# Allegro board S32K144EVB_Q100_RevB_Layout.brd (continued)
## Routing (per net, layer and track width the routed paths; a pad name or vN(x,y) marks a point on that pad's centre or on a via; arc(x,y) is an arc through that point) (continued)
P3V3: length 35
  TOP w0.381: 49.22,30.18 U15.5 ; U15.5 49.22,29.71 ; U15.5 50.59,29.71 ; U15.5 49.22,30.66 ; U15.5 50.59,30.66 ; U15.5 49.9,29.65 ; U15.5 50.59,30.18 ; U15.5 49.9,30.71 ; TP13.1 44.15,26.79 ; TP13.1 43.68,26.89 ; TP13.1 44.15,25.85 ; TP13.1 44.25,26.32 ; TP13.1 43.68,25.75 ; TP13.1 43.11,26.32 ; TP13.1 43.21,26.79 ; TP13.1 43.21,25.85 ; 42.73,33.75 J10.1 ; J10.1 44.64,32.79 ; J10.1 42.73,32.79 ; J10.1 43.69,32.79 ; J10.1 43.69,34.7 ; J10.1 44.64,33.75 ; J10.1 42.73,34.7 ; J10.1 44.64,34.7 ; 47.08,33.65 R63.1 ; R63.1 47.85,34.29 ; R63.1 46.32,33.65 ; R63.1 46.32,34.29 ; R63.1 47.85,33.65 ; R63.1 46.7,33.65 ; 50.95,29.8 C24.1 ; C24.1 51.72,29.8 ; C24.1 52.1,29.8 ; C24.1 52.48,29.16 ; C24.1 52.48,29.8 ; C24.1 50.95,29.16
  L3_MIX w0.508: J3.7 35.52,6.15 ; J3.7 34.49,5.12 ; J3.7 36.31,5.91 ; J3.7 36.55,5.12 ; J3.7 34.73,5.91
  vias: v1(40.9,27.01) v1(40.89,26.22) v1(40.91,25.42)
P3V3_SDA: length 34.8
  TOP w0.254: 31.01,35.52 C19.1 30.5,36.03 ; C18.1 29.93,36.03 ; C18.1 29.42,36.54 ; C18.1 29.42,35.52 ; v1(30.04,45.2) 30.3,45.46 R15.1 ; U1.1 9.07,51.26 ; U2.7 28.45,46.1 v1(28.2,45.85) 28.54,45.51 U4.1 ; 30.51,37.11 R52.1 ; 9.19,49.94 C3.1 ; U9.5 v1(33.7,39.65) ; v1(27.83,41.93) 27.86,41.93 28.13,41.66 U7.1 ; U8.11 v1(16.65,37.9) ; U8.1 v1(19.51,43.09) ; 15.64,40.52 16.01,40.88 16.58,40.88 16.94,40.52 ; R1.2 v1(6.4,52.28) ; U10.1 v1(27.41,38.62) ; 9.19,50.89 R3.1
  TOP w0.508: R60.1 v1(11.75,37.33) ; v1(37.61,42.64) C10.1 37.61,41.46 R39.2 R42.1 ; R77.1 v1(15.03,27.14) ; 15.64,40.52 C12.1 13.35,40.52 J9.1 ; C26.1 J12.1 ; R12.1 v1(25.56,46.72) ; R30.1 v1(30.99,42.98)
  TOP w0.635: v1(19.51,43.09) 18.65,43.95 C7.1 17.76,44.83 C6.1
  BOTTOM w0.254: 17.32,27.42 J12.1 17.99,28.09 ; J9.1 12.69,38.9 ; J9.1 10.78,38.9 ; J9.1 11.73,37.94
  vias: v1(8.76,50.56) v1(29.29,36.97)
P5V0: length 36.2
  TOP w0.254: 43.47,29.71 R169.1 ; R169.1 43.89,29.8 ; R169.1 44.31,29.71 ; R169.1 43.38,29.29
  TOP w0.381: 37.99,30.48 TP14.1 ; TP14.1 38.92,30.48 ; TP14.1 38.92,29.54 ; TP14.1 39.03,30.01 ; TP14.1 38.46,30.58 ; C22.1 42.88,29.83 ; C22.1 41.36,29.83 ; C22.1 42.12,30.47 ; C22.1 42.88,30.47 ; C22.1 41.36,30.47 ; 38.61,35.53 R64.1 ; R64.1 37.98,36.29 ; R64.1 37.98,35.53 ; U15.1 47.31,30.71 ; U15.1 48,30.18 ; U15.1 46.63,30.66 ; U15.1 46.63,30.18 ; U15.1 48,30.66 ; J10.3 38.61,34.7 ; J10.3 37.65,33.75 ; J10.3 37.87,34.48 ; J10.3 38.61,32.79 ; J10.3 39.34,33.01 ; J10.3 37.87,33.01 ; C21.1 41.07,29.83 ; C21.1 41.07,30.47 ; C21.1 39.54,29.83 ; C21.1 40.3,30.47 ; C21.1 39.54,30.47
  TOP w0.508: D4.A v2(30.01,29.88)
  L3_MIX w0.508: J3.9 38.85,5.91 ; J3.9 38.06,6.15 ; J3.9 39.09,5.12
  BOTTOM w0.254: 37.65,33.75 J10.3 ; J10.3 39.56,33.75 ; J10.3 38.61,32.79 ; 30.71,33.75 J107.2 ; J107.2 31.66,32.8 ; J107.2 32.61,33.75
  vias: v1(42.3,30.8) v1(43.1,31.39) v1(43.08,30.51) v2(38.62,31.09)
P5V0_SDA_USB_CONN_VBUS: length 5.6
  TOP w0.356: 5.64,42.72 J7.1
  TOP w0.635: 5.64,42.72 6.92,41.44 U6.1 L1.1
P5V_SDA: length 24.5
  TOP w0.254: v1(16.62,41.43) 16.74,41.43 U8.6 ; 22.67,45.86 R14.1 22.16,45.36
  TOP w0.508: C11.1 v1(9.35,38.48) ; L1.2 v1(7.18,38.88) 7.18,37.79 7.5,37.47 C15.1 ; U11.1 v1(8.08,31.93) ; R70.1 v1(8.14,31.06) ; C25.1 v1(8.15,29.82) ; R57.1 v1(26.57,37.38)
  L3_MIX w0.635: v1(16.62,41.43) v1(16.62,45.82)
  BOTTOM w0.254: v1(22.02,45.89) 22.47,45.44 22.47,39.84 23.1,39.21 24.74,39.21 25.5,38.45 25.53,38.45 25.9,38.08 25.9,38.05 v1(26.57,37.38)
  vias: v1(7.36,46.09) v1(8.23,46.11) v1(9.16,46.11)
P5V_SDA_PSW: length 34.4
  TOP w0.508: v1(7.96,27.05) 7.26,27.75 7.26,34.41 8.08,35.23 U11.6
  BOTTOM w0.508: v1(7.96,27.05) 9.59,27.05 11.2,25.44 20.81,25.44 J107.3
VBATT: length 88
  TOP w0.381: 22.29,7.96 J16.1 ; J16.1 23.2,11.8 ; J16.1 23.2,10.84 ; J16.1 22.75,11.8 ; J16.1 23.2,7.96 ; J16.1 23.2,9.88 ; J16.1 22.29,11.8 ; J16.1 21.83,7.96 ; 26.4,10.48 D9.A ; D9.A 26.4,12.08 ; D9.A 25.55,10.5 ; D9.A 25.55,11.28 ; D9.A 25.98,10.49 ; D9.A 25.55,12.07 ; TP38.1 26.26,9.05 ; TP38.1 25.69,9.62 ; TP38.1 26.15,8.58 ; TP38.1 25.22,8.58 ; TP38.1 25.69,8.48 ; TP38.1 25.22,9.52 ; TP38.1 25.12,9.05 ; TP38.1 26.15,9.52
  TOP w0.508: R110.1 v1(45.2,14.57)
  BOTTOM w0.635: v1(45.2,14.57) 37.33,14.57 34.96,12.2 28.83,12.2 v2(26.61,9.98)
  BOTTOM w1.016: J11.2 4.8,31.29 4.8,14.56 12.16,7.2 v3(23.93,7.2)
VDD: length 106
  TOP w0.254: 103.64,13.82 D11.A3 ; D11.A3 104.83,14.81 ; D11.A3 104.83,12.83 ; 104.83,10.73 D11.A2 ; D11.A2 103.64,11.72 ; D11.A2 104.83,12.71 ; 104.83,8.63 D11.A1 ; D11.A1 103.64,9.62 ; D11.A1 104.83,10.61
  TOP w0.508: J10.2 42.1,33.75 ; J10.2 41.88,34.48 ; J10.2 40.19,33.75 ; J10.2 40.41,34.48 ; J10.2 41.15,34.7 ; R64.2 40.77,36.29 ; R64.2 40.13,37.05 ; R64.2 40.13,35.53 ; J15.1 52.57,36.39 ; J15.1 51.62,36.39 ; J15.1 50.67,36.39 ; J15.1 52.57,35.44 ; J15.1 50.67,35.44 ; R121.1 48.93,37.77 ; R121.1 48.17,37.13 ; R121.1 47.4,37.77 ; 42.73,37.13 TP9.1 ; TP9.1 42.95,37.87 ; TP9.1 44.42,36.4 ; TP9.1 43.69,36.18 ; TP9.1 44.42,37.87 ; TP9.1 43.69,38.09 ; TP9.1 44.64,37.13 ; TP9.1 42.95,36.4 ; 48.28,35.81 R117.1 ; R117.1 49.8,35.81 ; R117.1 49.04,36.45 ; R63.2 47.85,35.81 ; R63.2 46.32,35.81 ; R63.2 47.08,36.45 ; 53.16,38.62 J14.1 ; J14.1 53.83,39.29 ; J14.1 53.83,38.62 ; J25.4 v2(99.68,33.62) ; 40.46,37.55 SH1.2 41.15,38.15 ; SW2.4 v1(105.08,30.97) ; SW3.2 v1(105.08,27.21) ; R56.2 v1(34.58,10.46) ; SW2.2 v1(105.08,38.79) ; SW3.4 v1(105.08,19.63)
  TOP w0.635: v2(94.05,35.92) J25.1 ; J3.3 C49.1
  L3_MIX w0.508: J3.3 31.23,5.91 ; J3.3 29.65,4.33 ; J3.3 29.41,5.12 ; J3.3 31.47,5.12 ; J3.3 29.65,5.91 ; J3.3 31.23,4.33 ; J3.3 30.44,4.09 ; J3.3 30.44,6.15 ; J10.2 41.88,33.01 ; J10.2 42.1,33.75 ; J10.2 40.19,33.75 ; J10.2 40.41,33.01 ; J10.2 40.41,34.48 ; J10.2 41.88,34.48 ; J10.2 41.15,32.79 ; J10.2 41.15,34.7 ; 42.73,37.13 TP9.1 ; TP9.1 42.95,37.87 ; TP9.1 43.69,38.09 ; TP9.1 43.69,36.18 ; TP9.1 42.95,36.4
  BOTTOM w0.508: J6.10 82.27,55.92 ; J6.10 81.24,54.89 ; J6.10 80.21,55.92 ; J6.10 81.24,56.95 ; 104.47,28.25 TP16.1 ; TP16.1 105.42,29.2 ; TP16.1 103.51,29.2 ; TP16.1 104.47,30.16 ; TP4.1 101.71,51.62 ; TP4.1 100.76,50.66 ; TP4.1 100.76,52.57 ; TP4.1 99.81,51.62 ; 82.75,2.58 J5.10 ; J5.10 83.78,3.61 ; J5.10 84.81,2.58 ; J5.10 83.78,1.55 ; 100.74,47.6 R13.1 ; R13.1 101.76,48.62 ; R13.1 101.76,46.59 ; R13.1 102.78,47.6
  BOTTOM w0.635: 102.88,34.66 100.73,34.66 v2(99.68,33.62) 96.35,33.62 v2(94.05,35.92)
  vias: v1(70.12,3.11) v1(70.13,2.07) v1(70.11,1.03) v1(71.49,2.07) v1(71.57,3.08) v1(71.58,1.03) v1(103.39,14.2) v1(103.39,11.98) v1(104.21,15.06) v1(104.23,8.3)
VDD_MCU: length 70.8
  TOP w0.254: C43.1 59.51,39.33 ; C43.1 58.87,39.33 ; C43.1 59.51,38.57 ; C43.1 58.87,37.81 ; C43.1 59.51,37.81 ; R103.1 58.95,33.62 ; R103.1 58.18,33.62 ; R103.1 58.95,32.98 ; R103.1 57.42,33.62 ; R103.1 57.42,32.98 ; 60.97,33.2 C144.1 ; C144.1 61.91,32.78 ; C144.1 61.06,32.78 ; C144.1 61.48,32.69 ; C144.1 61.99,33.2 ; C144.1 61.06,33.63 ; 63.24,32.78 C145.1 ; C145.1 64.09,32.78 ; C145.1 64.18,33.2 ; C145.1 63.16,33.2 ; C145.1 63.67,32.69 ; C147.1 59.51,40.3 ; C147.1 59.51,41.83 ; C147.1 58.23,40.3 ; C147.1 58.87,41.83 ; C147.1 58.23,41.06 ; C147.1 58.23,41.83 ; C147.1 59.51,41.06 ; C147.1 58.87,40.3 ; R99.1 60.56,33.63 ; R99.1 60.56,32.99 ; R99.1 59.04,33.63 ; R99.1 59.04,32.99 ; R99.1 59.8,33.63 ; 75.87,38.75 U17.87 ; C129.1 59.51,35.22 ; C129.1 59.51,34.46 ; C129.1 59.51,35.98 ; C129.1 58.87,34.46 ; C129.1 58.87,35.98 ; 84.68,28.16 U17.61 81.54,28.16 ; C140.1 63.08,33.2 ; C140.1 62.15,32.78 ; C140.1 62.58,32.69 ; C140.1 63,32.78 ; C140.1 62.07,33.2 ; C131.1 59.51,36.13 ; C131.1 58.87,37.66 ; C131.1 59.51,36.89 ; C131.1 59.51,37.66 ; C131.1 58.87,36.13 ; 75.37,19.77 U17.38
  TOP w0.381: 84.68,28.16 84.91,28.39 C143.1 ; C141.1 75.62,19.51 75.37,19.77 ; C142.1 75.62,39 75.87,38.75
  TOP w0.508: C146.1 86.48,28.55 86.31,28.39 C143.1
  TOP w0.635: C141.1 75.62,18.53 v2(75.2,18.11) 75.24,18.07 C137.1 ; v2(75.12,28.16) 81.54,28.16 ; C142.1 v2(75.62,40.4) 75.62,41.02 C133.1
  TOP w0.762: R117.2 49.17,34.29 50.56,32.9 J15.2
  BOTTOM w0.508: v1(68.89,30.41) v2(65.79,30.41)
  BOTTOM w1.016: J15.2 53.23,32.9 54.28,33.95 v3(57.38,33.95)
  vias: v2(75.12,30.66)
VIN: length 26.4
  TOP w0.762: D13.A J3.15 44.18,6.62 36.82,6.62 34.16,9.29 29.68,9.29 27.9,7.51 J3.1
ADC0_SE12: length 59.1
  TOP w0.16: R13.2 C5.1 97.69,44.54 97.69,44.54 TP5.1 v1(97.69,42.01) ; R164.2 v1(80.45,13.79)
  L3_MIX w0.16: v1(97.69,42.01) 102.17,37.53 102.17,31.06 102.77,30.46 102.77,18.33 99.99,15.55 v1(96.99,15.55)
  BOTTOM w0.16: v1(96.99,15.55) 95.1,13.65 89.65,13.65 89,14.3 85.66,14.3 84.82,13.47 80.78,13.47 v1(80.45,13.79)
AREF: length 44.2
  TOP w0.508: R109.2 55.67,44.7 53.32,47.06 35.01,47.06 32.76,49.31 26.69,49.31 23.84,52.16 J2.15
BTN0: length 50.2
  TOP w0.16: R152.2 v1(84.64,14.09) ; SW2.3 SW2.1 C16.1 R44.1 v1(100.03,38.61)
  L3_MIX w0.16: v1(99.26,17.01) 102.15,19.91 102.15,29.99 101.53,30.62 101.53,37.11 v1(100.03,38.61)
  BOTTOM w0.16: v1(84.64,14.09) 85.45,14.9 89.27,14.9 89.55,14.62 95.02,14.62 97.41,17.01 v1(99.26,17.01)
BTN1: length 36.6
  TOP w0.16: v1(95.45,19.7) R74.1 C28.1 SW3.3 SW3.1 ; R153.2 v1(82.96,12.3)
  L3_MIX w0.16: v1(95.45,12.71) v1(95.45,19.7)
  BOTTOM w0.16: v1(95.45,12.71) 85.8,12.71 85.39,12.3 v1(82.96,12.3)
CAN_HI: length 11.4
  TOP w0.406: J13.1 TP19.1 7.66,21.69 R92.1 L4.2
CAN_LO: length 11.3
  TOP w0.381: L4.4 R98.1
  TOP w0.406: J13.2 TP22.1 9.65,20.7 10.96,19.39 R98.1
ELEC_IN0: length 18.7
  TOP w0.16: R172.1 88.02,43.99 88.66,44.63 v1(91.94,44.63) ; J25.3 v1(91.41,33.62)
  L3_MIX w0.16: v1(91.41,33.62) 91.41,39.78 91.94,40.31 v1(91.94,44.63)
ELEC_IN1: length 16.7
  TOP w0.16: J25.5 v1(91.98,32.35) ; v1(92.9,43.33) R173.1
  L3_MIX w0.16: v1(91.98,32.35) 91.98,37.78 92.9,38.71 v1(92.9,43.33)
ELEC_IN2: length 11.2
  TOP w0.16: R174.1 v1(90.66,24.82) ; v1(91.43,31.08) J25.7
  L3_MIX w0.16: v1(90.66,24.82) 90.66,29.16 91.43,29.93 v1(91.43,31.08)
ELEC_IN4: length 15
  TOP w0.16: R175.1 90.05,19.79 90.05,19.78 v1(91.39,19.78) ; J25.9 v1(92.08,29.81)
  L3_MIX w0.16: v1(91.39,19.78) 91.39,29.13 v1(92.08,29.81)
ELEC_IN5: length 26.7
  TOP w0.16: R176.1 90.03,18.11 90.94,19.02 v1(99.46,19.02) ; J25.10 v1(101.41,29.81)
  L3_MIX w0.16: v1(101.41,29.81) 101.41,20.97 v1(99.46,19.02)
ELEC_IN9: length 24.7
  TOP w0.16: J25.14 v1(99.6,27.27) ; v1(99.31,39.3) 90.74,39.3 90.07,38.63 R179.1
  L3_MIX w0.16: v1(99.6,27.27) 99,27.87 99,35.31 99.31,35.63 v1(99.31,39.3)
ELEC_IN10: length 17.7
  TOP w0.16: R180.1 90.07,36.96 90.57,37.46 v1(92.68,37.46) ; J25.15 v1(91.99,26)
  L3_MIX w0.16: v1(92.68,37.46) 93.15,36.99 93.15,27.16 v1(91.99,26)
JTAG_TCLK/SWD_CLK: length 81.5
  TOP w0.16: J8.2 43.87,44.19 TP31.1 47.49,40.56 J14.4 ; R127.2 v1(69.45,44.33) ; R143.1 v1(86.06,21.46)
  L3_MIX w0.16: v1(86.06,21.46) 84.4,23.12 84.4,30.46 85.53,31.59 85.53,34.9 87.49,36.86 87.49,38.72 87.14,39.08 v1(87.14,45.68)
  BOTTOM w0.16: v1(87.14,45.68) 76.87,45.68 74.78,43.6 70.18,43.6 v1(69.45,44.33) 67.96,42.85 59.52,42.85 54.57,37.89 51.8,37.89 51.02,38.66 51.02,39.7 J14.4
JTAG_TDI: length 36.1
  TOP w0.16: R140.1 v1(80.83,46.41) ; R120.2 v1(49.41,45.66) ; v1(71.12,44.36) R128.2
  BOTTOM w0.16: v1(80.83,46.41) 76.73,46.41 74.68,44.36 v1(71.12,44.36) 70.31,45.17 56.88,45.17 56.39,45.66 v1(49.41,45.66)
JTAG_TDO: length 36.7
  TOP w0.16: R123.2 73.37,43.98 73.37,43.98 v1(73.37,45.16) ; R119.2 v1(47.85,46.31) ; R141.1 v1(77.96,47.49)
  BOTTOM w0.16: v1(77.96,47.49) 76.28,47.49 73.96,45.16 v1(73.37,45.16) 72.75,45.16 71.58,46.33 57.35,46.33 56.74,46.94 48.48,46.94 v1(47.85,46.31)
JTAG_TMS/SWD_DIO_PTA4: length 75.1
  TOP w0.16: J14.2 R121.2 TP34.1 46.34,39.29 J106.2 ; v1(66.34,43.33) R122.2 ; R142.1 v1(77.18,10.96)
  L3_MIX w0.16: v1(66.34,43.33) 66.34,34.99 64.67,33.32 64.67,10.88 v1(65,10.56)
  BOTTOM w0.16: v1(65,10.56) 65.4,10.96 v1(77.18,10.96) ; J14.2 51.89,38.6 52.03,38.46 54.04,38.46 59.42,43.84 65.83,43.84 v1(66.34,43.33)
LEDRGB_BLUE: length 3.9
  TOP w0.16: R95.1 TP28.1 D11.C3
LEDRGB_GREEN: length 3.9
  TOP w0.16: R96.1 TP29.1 D11.C2
LEDRGB_RED: length 3.9
  TOP w0.16: D11.C1 TP30.1 R97.1
LIN: length 59.7
  TOP w0.406: U19.19 v1(34.87,16.32) ; J11.1 C17.1 5.51,26.48 TP18.1 8.31,25.89 9.16,26.74 R171.1
  TOP w0.457: R171.1 R80.1 v1(10.72,23.32)
  BOTTOM w0.457: v1(10.72,23.32) 11.33,23.32 11.74,23.73 21,23.73 24.1,26.82 30.95,26.82 33.48,24.3 33.48,17.71 v1(34.87,16.32)
LIN_MASTER: length 7.4
  TOP w0.406: R80.2 v1(16.97,24.72) D6.C
  TOP w0.508: R171.2 R80.2
LVLRST_EN: length 1.4
  TOP w0.16: R1.1 U1.5
MIC2005_CSLEW: length 1.8
  TOP w0.16: U11.5 C15.2
POWER_EN: length 15.7
  TOP w0.16: v1(20.95,42.96) 20.95,42.91 U8.31 ; R69.1 v1(12.64,32.91)
  BOTTOM w0.16: v1(12.64,32.91) 12.64,34.08 15.65,37.09 15.65,38.42 16.73,39.5 17.49,39.5 v1(20.95,42.96)
PTA0: length 12.6
  TOP w0.16: R172.2 88.01,41.81 v1(88.01,40.78) 87.49,40.26 86.85,40.26 85.46,38.87 80.49,38.87 79.87,38.25 U17.79
  BOTTOM w0.16: v1(88.01,40.78) 88.02,40.78 SH9.2
PTA1: length 13.6
  TOP w0.16: R173.2 v1(89.67,40.79) 88.57,39.7 87.08,39.7 85.79,38.4 80.81,38.4 80.37,37.97 U17.78
  BOTTOM w0.16: v1(89.67,40.79) 89.66,40.8 SH10.2
PTA2: length 23.6
  TOP w0.16: J25.11 v1(91.96,28.54) ; U17.73 v1(81.85,34.16)
  L3_MIX w0.16: v1(91.96,28.54) 92.69,29.27 v1(92.69,35.9)
  BOTTOM w0.16: v1(92.69,35.9) 91.94,35.9 90.79,34.75 86.34,34.75 85.75,34.16 84.73,34.16 84.71,34.17 84.29,34.17 84.28,34.16 v1(81.85,34.16) ; v1(91.96,28.54) SH11.1
PTA3: length 25.5
  TOP w0.16: J25.12 v1(100.13,28.54) ; U17.72 v1(84.5,33.66)
  L3_MIX w0.16: v1(99.92,31.74) 100.27,31.39 100.27,29.13 100.13,29 v1(100.13,28.54)
  BOTTOM w0.16: v1(100.13,28.54) SH12.1 ; v1(84.5,33.66) 86.21,33.66 86.93,34.37 92.35,34.37 94.99,31.74 v1(99.92,31.74)
PTA4: length 63.6
  TOP w0.16: R122.1 v1(67.77,40.82) 70.37,38.21 U17.98
  L3_MIX w0.16: v1(69.4,12.78) 69.4,23.28 69.88,23.77 69.88,34.84 67.77,36.96 v1(67.77,40.82)
  BOTTOM w0.16: v1(69.4,12.78) 54.95,12.78 47.04,4.86 47.04,3.93 J3.16
PTA6: length 6.5
  TOP w0.16: U17.58 84.52,26.66 86.36,24.82 R174.2 R147.2
PTA7: length 27.7
  TOP w0.16: U17.57 84.35,26.16 v1(84.85,25.65) ; J25.8 v1(99.59,31.08)
  L3_MIX w0.16: v1(99.59,31.08) 99.59,28.24 100.23,27.59 100.23,25.28 v1(99.89,24.94)
  BOTTOM w0.16: v1(99.59,31.08) SH8.2 ; v1(84.85,25.65) 90.92,25.65 91.22,25.35 92.98,25.35 93.62,25.99 98.84,25.99 v1(99.89,24.94)
PTA8: length 17.5
  TOP w0.16: U17.100 v1(69.37,38.38)
  L3_MIX w0.16: J6.17 71.08,49.95 70.61,49.48 70.61,43.65 68.95,41.99 68.95,38.79 v1(69.37,38.38)
PTA9: length 20.7
  TOP w0.16: U17.99 v1(69.87,35.64)
  L3_MIX w0.16: J6.19 68.54,50.51 70,49.05 70,43.89 68.57,42.46 68.57,37.89 69.87,36.59 v1(69.87,35.64)
PTA10: length 67.3
  TOP w0.16: U17.92 v1(73.37,40.8) R123.1
  L3_MIX w0.16: v1(73.93,17.45) 73.37,18.01 73.37,23.22 72.72,23.87 72.72,40.16 v1(73.37,40.8)
  BOTTOM w0.16: v1(73.93,17.45) 73.93,16.99 72.62,15.68 71.54,15.68 70.58,14.72 63.6,14.72 63.25,14.37 53.91,14.37 45.99,6.44 45.12,6.44 44.51,5.84 44.51,3.95 J3.14
PTA11: length 31
  TOP w0.16: U17.91 v1(73.87,38.2)
  L3_MIX w0.16: v1(61.41,40.4) 61.41,51.22 62.14,51.95 62.14,54.6 J1.2
  BOTTOM w0.16: v1(61.41,40.4) 61.79,40.02 64.59,40.02 65.53,39.07 73,39.07 v1(73.87,38.2)
PTA12: length 20.8
  TOP w0.16: U17.90 v1(74.37,38.9)
  L3_MIX w0.16: J6.16 72.46,54.75 72.46,52.06 74.95,49.58 74.95,45.69 74.37,45.11 v1(74.37,38.9)
PTA13: length 20
  TOP w0.16: U17.89 v1(74.87,38.2)
  L3_MIX w0.16: J6.14 74.92,54.67 74.92,52.41 75.45,51.87 75.45,45.13 74.87,44.55 v1(74.87,38.2)
PTA14: length 65.9
  TOP w0.16: U17.88 75.37,38.55 74.38,39.54 v1(74.38,46.62)
  BOTTOM w0.16: v1(74.38,46.62) 73.47,46.62 72.66,47.43 58.35,47.43 57.44,48.34 37.62,48.34 34.64,51.32 26.14,51.32 25.14,52.32 25.14,54.62 J2.16
PTA15: length 6.9
  TOP w0.16: U17.83 77.87,38.12 78.14,38.38 78.14,39.54 79.48,40.89 80.26,40.89 81.18,41.81 R167.1
PTA16: length 7.9
  TOP w0.16: U17.82 78.37,37.94 78.54,38.11 78.54,39.22 79.64,40.33 81.38,40.33 82.86,41.81 R165.1
PTA17: length 53.7
  TOP w0.16: U17.62 82.07,28.66 v1(81.03,29.69)
  L3_MIX w0.16: J1.4 59.63,54.63 59.63,52.92 58.73,52.02 v1(58.73,30.47)
  BOTTOM w0.16: v1(81.03,29.69) 77.8,29.69 77.58,29.48 71.62,29.48 69.96,27.81 66.94,27.81 65.82,28.93 59.24,28.93 58.73,29.44 v1(58.73,30.47)
PTB0: length 9.4
  TOP w0.16: U17.54 84.79,24.66 85.55,23.89 85.55,20.19 v1(85.96,19.79) R175.2
  BOTTOM w0.16: SH5.1 86.43,19.79 86.42,19.79 v1(85.96,19.79)
PTB1: length 10.2
  TOP w0.16: U17.53 84.37,24.16 85.07,23.45 85.07,19.54 v1(85.91,18.71) 86.51,18.11 R176.2
  BOTTOM w0.16: v1(85.91,18.71) 86.31,18.31 SH4.1
PTB2: length 85.9
  TOP w0.16: J2.11 28.92,51.95 30.15,50.71 33.17,50.71 35.23,48.65 54.89,48.65 56.07,47.47 71.28,47.47 72.33,48.51 v1(79.51,48.51) ; U17.48 v1(80.37,19.63)
  L3_MIX w0.16: v1(79.51,48.51) 79.52,48.5 79.52,42.48 80.33,41.67 80.33,34.78 79.67,34.12 79.67,24.38 80.37,23.68 v1(80.37,19.63)
PTB3: length 80.7
  TOP w0.16: J2.9 31.46,52.25 32.04,51.67 33.68,51.67 35.62,49.73 71.67,49.73 73.3,51.36 v1(79.03,51.36) ; U17.47 79.89,21.42 v1(79.89,22.84)
  L3_MIX w0.16: v1(79.89,22.84) 79.25,23.48 79.25,42.03 79.03,42.24 v1(79.03,51.36)
PTB4: length 67.9
  TOP w0.16: J2.7 36.5,50.88 60.7,50.88 61.77,51.94 v1(67.83,51.94) ; v1(69.06,24.9) 69.53,24.9 70.37,24.05 U17.28
  L3_MIX w0.16: v1(69.06,24.9) 69.43,25.26 69.43,34.48 67.31,36.6 67.31,41.57 67.83,42.09 v1(67.83,51.94)
PTB5: length 83.8
  TOP w0.16: v1(63.48,15.95) 63.48,16.56 66.68,19.76 69.45,19.76 69.87,20.18 U17.27
  L3_MIX w0.16: J2.5 36.54,51.01 39.26,48.29 42.73,48.29 44.88,46.14 44.88,30.86 43.96,29.94 43.96,8.43 v1(44.72,7.66)
  BOTTOM w0.16: v1(63.48,15.95) 62.97,15.95 62.41,15.38 53.46,15.38 45.74,7.66 v1(44.72,7.66)
PTB6: length 6.6
  TOP w0.16: R81.2 62.92,26.3 R84.1 65.54,27.08 66.12,27.66 U17.16
PTB6_XTAL: length 6.9
  TOP w0.16: R84.2 60.38,27.08 60.33,27.13 R91.2 59.42,27.13 58.96,26.66 58.58,26.66 C127.1 57.24,26.92 Y3.2
PTB7: length 6.6
  TOP w0.16: R90.2 62.92,29.51 R88.1 65.57,28.73 66.14,28.16 U17.15
PTB7_EXTAL: length 6.9
  TOP w0.16: R88.2 60.4,28.73 60.33,28.65 R91.1 59.42,28.65 58.96,29.11 58.6,29.11 C126.1 57.27,28.92 Y3.1
PTB8: length 45.8
  TOP w0.16: v1(85.21,37.7) 82.54,37.7 82.21,38.04 81.07,38.04 80.87,37.83 U17.77
  L3_MIX w0.16: v1(85.21,37.7) v1(85.21,49.6)
  BOTTOM w0.16: J1.5 59.64,52.12 60.37,52.12 61.18,51.31 78.23,51.31 79.94,49.6 v1(85.21,49.6)
PTB9: length 45.6
  TOP w0.16: v1(84.41,36.91) U17.76
  L3_MIX w0.16: v1(84.41,48.88) 84.41,46.22 84.17,45.99 84.17,39.62 84.41,39.38 v1(84.41,36.91)
  BOTTOM w0.16: v1(84.41,48.88) 79.91,48.88 78.15,50.64 59.75,50.64 59.24,51.15 58.07,51.15 J1.7
PTB10: length 49.9
  TOP w0.16: U17.75 v1(83.12,36.43)
  L3_MIX w0.16: J1.9 53.3,49.63 54.72,48.22 54.72,36.19 v1(54.39,35.86)
  BOTTOM w0.16: v1(54.39,35.86) 56.77,35.86 59.08,38.17 67.72,38.17 68.65,37.23 82.32,37.23 v1(83.12,36.43)
PTB11: length 54
  TOP w0.16: U17.74 v1(84.48,34.66)
  L3_MIX w0.16: v1(54.84,32.82) 54.84,34.51 53.91,35.45 53.91,46.89 50.76,50.04 J1.11
  BOTTOM w0.16: v1(54.84,32.82) 58.63,32.82 59.37,33.57 74.42,33.57 75.51,34.66 81.62,34.66 81.63,34.67 82.06,34.67 82.07,34.66 v1(84.48,34.66)
PTB12: length 10
  TOP w0.16: U17.68 84.88,31.66 85.52,32.29 85.52,35.61 v1(86.87,36.96) R180.2
  BOTTOM w0.16: v1(86.87,36.96) 86.87,36.96 SH15.1
PTB13: length 25.3
  TOP w0.16: U17.67 v1(84.41,31.16) ; J25.16 v1(99.57,26)
  BOTTOM w0.16: v1(84.41,31.16) 90.7,31.16 91.08,31.54 92.77,31.54 93.93,30.38 95.96,30.38 96.71,29.63 100.33,29.63 100.79,29.18 SH16.2 100.17,25.99 100.17,26 v1(99.57,26)
PTB14: length 67
  TOP w0.16: U17.66 84.71,30.66 85.97,31.92 85.97,33.59 86.87,34.48 v1(86.87,35.27) 87.25,35.27 R124.1
  L3_MIX w0.16: v1(86.87,35.27) 86.06,34.46 86.06,31.42 85.39,30.75 85.39,24.36 86.53,23.22 v1(86.53,12.13)
  BOTTOM w0.16: v1(86.53,12.13) 86.2,11.8 83.19,11.8 83.18,11.79 82.75,11.79 82.74,11.8 82.48,11.8 82,12.28 64.48,12.28 62.44,10.23 62.44,9.18 59.76,6.51 59.76,3.96 J4.8
PTB15: length 61.9
  TOP w0.16: R125.1 87.25,33.6 v1(86.96,33.6) 86.96,33.07 86.46,32.57 86.46,31.46 85.15,30.16 U17.65
  L3_MIX w0.16: v1(86.96,33.6) 86.54,33.18 86.54,31.28 85.91,30.66 85.91,25.23 87.09,24.04 87.09,11.12 v1(85.91,9.93)
  BOTTOM w0.16: v1(85.91,9.93) 85.58,10.26 79.56,10.26 79.08,9.78 65.84,9.78 62.33,6.27 62.33,3.99 J4.10
PTB16: length 57.9
  TOP w0.16: U17.64 85.45,29.66 87.01,31.21 v1(87.01,31.93) R126.1
  L3_MIX w0.16: v1(86.99,9.77) 87.62,10.39 87.62,24.72 86.96,25.37 86.96,29 86.34,29.62 86.34,30.45 87.01,31.11 v1(87.01,31.93)
  BOTTOM w0.16: J4.12 64.81,3.93 64.81,6.41 66.76,8.36 78.95,8.36 80.37,9.78 82.36,9.78 83.03,9.11 86.33,9.11 v1(86.99,9.77)
PTB17: length 62.9
  TOP w0.16: J4.6 57.12,3.85 57.12,6.5 58.84,8.22 64.27,8.22 67.28,11.23 74.48,11.23 75.97,9.73 77.74,9.73 78.97,10.96 87.04,10.96 v1(88.15,12.08) ; R129.2 86.98,30.25 v1(86.88,30.15) 85.89,29.16 U17.63
  L3_MIX w0.16: v1(88.15,12.08) 88.15,25.6 87.47,26.29 87.47,29.57 v1(86.88,30.15)
PTC0: length 5.2
  TOP w0.16: R146.2 77.18,19.56 76.37,20.37 U17.40
PTC1: length 29.8
  TOP w0.16: v1(76.87,6.26) 77.9,6.26 78.52,6.88 88.14,6.88 88.86,6.16 J5.13 ; v1(76.22,16.26) 76.22,19.96 75.87,20.31 U17.39
  L3_MIX w0.16: v1(76.87,6.26) 76.87,6.79 75.42,8.24 75.42,13.46 76.22,14.27 v1(76.22,16.26)
PTC2: length 35.8
  TOP w0.16: v1(71.06,9.32) 73.05,7.33 77.28,7.33 77.77,7.82 89.74,7.82 91.4,6.16 J5.15 ; v1(71.37,20.09) U17.30
  L3_MIX w0.16: v1(71.06,9.32) 71.06,14.54 71.68,15.17 71.68,16.01 71.16,16.54 71.16,17.79 71.37,18 v1(71.37,20.09)
PTC3: length 24.9
  TOP w0.16: J4.16 67.19,3.93 v1(67.19,6.72) ; U17.29 70.87,20.17 69.85,19.15 68.31,19.15 v1(66.52,17.36) R132.2 65.74,16.47 R163.1
  L3_MIX w0.16: v1(67.19,6.72) 67.19,14.95 66.52,15.62 v1(66.52,17.36)
PTC4: length 67.9
  TOP w0.16: U17.96 71.37,39 v1(69.45,40.92) R127.1
  L3_MIX w0.16: v1(70.72,15.77) 70.39,16.1 70.39,38.43 69.45,39.37 v1(69.45,40.92)
  BOTTOM w0.16: v1(70.72,15.77) 70.3,15.36 63.4,15.36 62.86,14.82 53.66,14.82 45.87,7.04 43.4,7.04 41.8,5.44 41.8,3.78 J3.12
PTC5: length 65.7
  TOP w0.16: R128.1 v1(71.12,40.83) 71.12,40.11 71.87,39.36 U17.95
  L3_MIX w0.16: v1(71.13,22.99) 71.13,40.37 71.12,40.37 v1(71.12,40.83)
  BOTTOM w0.16: v1(71.13,22.99) 70.38,22.99 65.38,17.99 61.84,17.99 60.82,16.96 54.16,16.96 45.53,8.33 41.91,8.33 39.27,5.69 39.27,3.79 J3.10
PTC6: length 76.8
  TOP w0.16: U17.81 78.87,38.93 79.74,39.79 83.5,39.79 v1(84.63,40.93) 84.66,40.96 R161.1
  L3_MIX w0.16: v1(63.41,41.18) 63.41,19.66 63.92,19.15 63.92,17.36 61.59,15.04 v1(61.59,9.42)
  BOTTOM w0.16: v1(61.59,9.42) 57.97,9.42 54.47,5.93 54.47,3.75 J4.4 ; v1(63.41,41.18) 66.44,41.18 67.49,40.14 74.01,40.14 74.8,40.93 76.41,40.93 76.42,40.94 76.85,40.94 76.86,40.93 v1(84.63,40.93)
PTC7: length 80.9
  TOP w0.16: U17.80 79.37,38.57 80.19,39.39 84.86,39.39 v1(86.34,40.87) R162.1 ; J4.2 52.04,3.85 52.04,6.96 55.29,10.22 v1(60.25,10.22)
  L3_MIX w0.16: v1(60.25,10.22) 60.25,14.5 62.75,17 v1(62.75,40.6)
  BOTTOM w0.16: v1(62.75,40.6) 65.47,40.6 66.46,39.61 85.08,39.61 v1(86.34,40.87)
PTC8: length 31.2
  TOP w0.16: U17.56 v1(80.59,25.66)
  L3_MIX w0.16: v1(80.59,25.66) 80.59,30.79 80.87,31.06 80.87,42.04 80.02,42.88 80.02,52.16 J6.9
PTC9: length 33.7
  TOP w0.16: v1(78.4,25.97) 79.16,25.97 79.97,25.16 U17.55
  L3_MIX w0.16: J6.11 78.7,52.24 77.47,51.01 77.47,46.98 78.63,45.82 78.63,28.94 78.86,28.7 78.86,26.43 v1(78.4,25.97)
PTC10: length 9.5
  TOP w0.16: R133.2 87.16,16.56 84.63,19.09 84.63,23.18 84.15,23.66 U17.52
PTC11: length 10.5
  TOP w0.16: U17.51 83.12,19.76 85.58,17.3 85.58,15.68 86.51,14.76 R134.2
PTC12: length 96.5
  TOP w0.16: J2.10 32.8,54.58 32.8,52.69 33.33,52.16 34.02,52.16 35.85,50.33 68.26,50.33 69.83,51.9 v1(81.65,51.9) ; U17.50 81.37,20.13 83.98,17.52 v1(84.59,17.52) 84.59,16.56 R152.1
  L3_MIX w0.16: v1(81.65,51.9) 81.65,49.53 83.51,47.67 83.51,37.19 83.75,36.96 83.75,18.37 v1(84.59,17.52)
PTC13: length 94.2
  TOP w0.16: v1(81.53,48.21) 80.54,49.19 35.33,49.19 33.34,51.18 31.31,51.18 30.18,52.31 30.18,54.66 J2.12 ; U17.49 80.87,19.61 v1(82.96,17.52) 82.96,17.16 R153.1
  L3_MIX w0.16: v1(81.53,48.21) 81.53,45.72 82.34,44.91 82.34,35.51 82.96,34.88 v1(82.96,17.52)
PTC14: length 32.4
  TOP w0.16: R164.1 v1(80.45,17.55) 79.37,18.63 U17.46
  L3_MIX w0.16: v1(80.45,17.55) 79.91,17.01 79.91,12.58 80.24,12.25 v1(80.24,8.85)
  BOTTOM w0.16: v1(80.24,8.85) 78.76,7.37 68.88,7.37 67.19,5.68 67.19,3.77 J4.14
PTC15: length 34.8
  TOP w0.16: v1(78.87,8.94) 79.71,9.78 82.35,9.78 83.32,8.8 92.57,8.8 95.27,6.1 95.27,3.79 J5.20 ; U17.45 v1(78.87,18.1)
  L3_MIX w0.16: v1(78.87,18.1) v1(78.87,8.94)
PTC16: length 66.7
  TOP w0.16: J6.8 85,54.7 85,51.86 89.46,47.41 v1(94.96,47.41) ; U17.44 v1(78.37,23.95)
  L3_MIX w0.16: v1(98.65,22.39) 97.53,23.51 97.53,37.92 94.96,40.49 v1(94.96,47.41)
  BOTTOM w0.16: v1(98.65,22.39) 96.81,24.23 94.42,24.23 94.01,23.82 88.84,23.82 88.71,23.95 v1(78.37,23.95)
PTC17: length 68.1
  TOP w0.16: U17.43 77.87,24.43 v1(78.38,24.94) ; J6.6 87.53,54.71 87.53,51.61 90.1,49.03 v1(96.62,49.03)
  L3_MIX w0.16: v1(96.62,49.03) 96.62,41.35 98.52,39.45 98.52,25.14 v1(99.94,23.72)
  BOTTOM w0.16: v1(78.38,24.94) 88.55,24.94 89.21,24.27 93.26,24.27 94.03,25.04 98.62,25.04 v1(99.94,23.72)
PTD0: length 85.9
  TOP w0.16: R156.1 v1(63.93,39.29) 66.12,37.1 66.12,34.04 66.51,33.66 U17.4
  L3_MIX w0.16: v1(63.93,39.29) v1(63.93,48.06) ; J6.1 v1(91.4,45.9)
  BOTTOM w0.16: J2.6 37.83,54.62 37.83,51.58 40.35,49.07 57.91,49.07 58.92,48.06 v1(63.93,48.06) 78.94,48.06 79.54,47.46 89.84,47.46 v1(91.4,45.9)
PTD1: length 49
  TOP w0.16: U17.3 v1(68.92,34.16)
  L3_MIX w0.16: J6.2 91.4,56.03 90.15,57.28 73.26,57.28 72.41,56.43 72.41,55.36 71.76,54.72 67.88,54.72 66.87,53.71 66.87,36.21 v1(68.92,34.16)
PTD2: length 21.3
  TOP w0.16: U17.71 v1(81.85,33.16) ; J25.13 v1(91.98,27.27)
  L3_MIX w0.16: v1(81.85,33.16) 81.85,31.47 82.09,31.22 82.09,26.99 81.85,26.75 v1(81.85,26.29)
  BOTTOM w0.16: v1(91.98,27.27) 91.75,27.03 SH13.2 90.92,26.42 90.79,26.29 v1(81.85,26.29)
PTD3: length 68.2
  TOP w0.16: U17.70 v1(84.43,32.66) ; J1.14 49.58,57.27 87.51,57.27 J6.4
  L3_MIX w0.16: J6.4 87.67,54.72 87.67,48.32 85.85,46.5 85.85,36.67 85.07,35.89 85.07,33.3 v1(84.43,32.66)
PTD4: length 10.9
  TOP w0.16: U17.69 84.58,32.16 85.06,32.64 85.06,36.74 v1(86.96,38.63) R179.2
  BOTTOM w0.16: v1(86.96,38.63) 86.96,38.63 SH14.1
PTD5: length 52.9
  TOP w0.16: U17.33 v1(72.87,22.82)
  L3_MIX w0.16: v1(72.87,22.82) 72.24,23.46 72.24,44.05 71.34,44.95 v1(71.34,48.64)
  BOTTOM w0.16: J1.12 52.2,54.48 52.2,51.98 54.47,49.71 58.61,49.71 59.68,48.64 v1(71.34,48.64)
PTD6: length 43.5
  TOP w0.16: v1(69.87,9.32) 70.34,9.8 71.84,9.8 73.29,8.35 91.44,8.35 92.75,7.05 92.75,3.77 J5.18 ; U17.32 72.37,19.42 70.33,17.39 v1(69.87,17.39) R130.2
  L3_MIX w0.16: v1(69.87,17.39) v1(69.87,9.32)
PTD7: length 42.8
  TOP w0.16: R131.2 v1(68.2,17.38) 69.38,18.56 70.5,18.56 71.87,19.93 U17.31 ; v1(68.65,9.31) 71.19,6.78 77.56,6.78 78.17,7.38 89.04,7.38 90.29,6.14 90.29,3.69 J5.16
  L3_MIX w0.16: v1(68.65,9.31) 68.2,9.77 v1(68.2,17.38)
PTD8: length 65.6
  TOP w0.16: J6.7 83.78,51.9 89.23,46.45 v1(94.12,46.45) ; U17.42 77.37,23.23 v1(76.1,24.5)
  L3_MIX w0.16: v1(94.12,46.45) 94.12,40.17 96.89,37.41 96.89,23.03 v1(97.58,22.34)
  BOTTOM w0.16: v1(76.1,24.5) 76.66,24.5 77.75,23.41 96.51,23.41 v1(97.58,22.34)
PTD9: length 68.2
  TOP w0.16: v1(95.73,48.1) 89.72,48.1 86.32,51.5 J6.5 ; U17.41 76.87,22.82 v1(76.11,23.58)
  L3_MIX w0.16: v1(95.73,48.1) 95.73,40.99 98.01,38.71 98.01,24.39 99.37,23.03 v1(99.37,21.45)
  BOTTOM w0.16: v1(99.37,21.45) 98.54,20.62 88.63,20.62 86.94,22.31 77.38,22.31 v1(76.11,23.58)
PTD10: length 66.4
  TOP w0.16: R166.1 73.36,17.09 v1(73.03,17.42) 73.03,18.64 74.37,19.98 U17.36
  L3_MIX w0.16: J1.6 57.09,54.62 57.09,44.53 58.21,43.41 58.21,24.33 55.13,21.24 v1(55.13,15.92)
  BOTTOM w0.16: v1(73.03,17.42) 72.2,16.59 62.99,16.59 62.32,15.92 v1(55.13,15.92)
PTD11: length 67.2
  TOP w0.16: R168.1 v1(71.69,17.44) 71.69,18.07 73.87,20.25 U17.35
  L3_MIX w0.16: J1.8 54.55,54.62 54.55,49.84 56.31,48.07 56.31,24.89 53.96,22.53 v1(53.96,15.91)
  BOTTOM w0.16: v1(53.96,15.91) 54.51,16.45 61.95,16.45 62.65,17.15 65.57,17.15 66.74,18.33 70.81,18.33 v1(71.69,17.44)
PTD12: length 52.9
  TOP w0.16: U17.34 v1(73.37,24.01)
  L3_MIX w0.16: v1(73.37,24.01) 73.37,39.36 73.9,39.89 v1(73.9,49.71)
  BOTTOM w0.16: J1.10 54.55,54.67 54.55,52.67 56.93,50.29 59.06,50.29 59.65,49.71 v1(73.9,49.71)
PTD13: length 62.2
  TOP w0.16: v1(58.67,18.49) 63.83,18.49 67.62,22.28 U17.25
  L3_MIX w0.16: J2.1 41.62,52.29 46.74,47.17 46.74,27.97 44.99,26.21 44.99,21.57 44.71,21.3 v1(44.71,20.15)
  BOTTOM w0.16: v1(58.67,18.49) 57.01,20.15 v1(44.71,20.15)
PTD14: length 61.8
  TOP w0.16: v1(59.64,19.23) 63.97,19.23 65.64,20.91 65.64,22.71 66.59,23.66 U17.24
  L3_MIX w0.16: v1(44.49,22.81) 44.49,29.67 45.51,30.69 45.51,46.37 42.42,49.46 41.24,49.46 39.08,51.63 J2.3
  BOTTOM w0.16: v1(59.64,19.23) 57.61,21.26 46.04,21.26 v1(44.49,22.81)
PTD15: length 62.8
  TOP w0.16: R154.1 v1(63.88,20.22) 63.88,20.68 64.72,21.52 64.72,22.73 66.65,24.66 U17.22
  L3_MIX w0.16: J2.2 42.36,55.18 42.36,55.16 43.61,53.91 43.61,51.2 47.3,47.5 47.3,27.64 45.45,25.79 v1(45.45,24.55)
  BOTTOM w0.16: v1(45.45,24.55) 45.45,23.67 46.92,22.2 59.01,22.2 60.35,20.87 63.23,20.87 v1(63.88,20.22)
PTD16: length 59.7
  TOP w0.16: U17.21 66.41,25.16 63.98,22.73 v1(63.98,21.85) 63.93,21.89 R155.1
  L3_MIX w0.16: v1(45.15,27.22) 45.15,29.45 46.14,30.44 46.14,46.74 40.26,52.62 40.26,54.73 J2.4
  BOTTOM w0.16: v1(45.15,27.22) 48.48,27.22 52.67,23.03 62.79,23.03 v1(63.98,21.85)
PTD17: length 37.6
  TOP w0.16: U17.20 v1(76.1,25.66)
  L3_MIX w0.16: J6.13 76.16,45.27 75.55,44.65 75.55,42.74 77.16,41.13 77.16,33.71 76.1,32.65 v1(76.1,25.66)
PTE0: length 65.5
  TOP w0.16: v1(71.97,45.15) 71.97,40.12 72.37,39.71 U17.94
  BOTTOM w0.16: v1(71.97,45.15) 71.38,45.15 70.79,45.74 57.17,45.74 56.63,46.27 49.1,46.27 48.48,45.66 46.6,45.66 45.5,46.75 36.72,46.75 33.38,50.09 22.04,50.09 J2.19
PTE1: length 63.8
  TOP w0.16: v1(72.49,46.48) 72.49,40.47 72.87,40.09 U17.93
  BOTTOM w0.16: J2.17 23.95,50.73 33.95,50.73 37.03,47.65 57.11,47.65 57.8,46.96 72.01,46.96 v1(72.49,46.48)
PTE2: length 5.4
  TOP w0.16: R145.2 77.83,41.81 77.37,41.35 77.37,38.87 76.87,38.37 U17.85
PTE3: length 56.9
  TOP w0.16: v1(46.58,24.24) 47.6,23.22 57.14,23.22 58.49,24.57 63.73,24.57 65.82,26.66 U17.18
  L3_MIX w0.16: J1.16 46.95,54.65 46.95,50.71 48.99,48.67 48.99,26.66 v1(46.58,24.24)
PTE4: length 31.1
  TOP w0.16: R137.2 63.64,35.94 63.65,35.94 v1(64.11,35.94) 65.15,34.89 65.15,31.94 65.94,31.16 U17.9
  L3_MIX w0.16: J6.20 67.15,55.92 65.13,53.9 65.13,36.96 v1(64.11,35.94)
PTE5: length 34.9
  TOP w0.16: R136.2 v1(64.05,37.62) 65.69,35.98 65.69,32.24 66.27,31.66 U17.8
  L3_MIX w0.16: J6.18 69.97,57.03 66.33,57.03 64.6,55.29 64.6,38.17 v1(64.05,37.62)
PTE6: length 5.9
  TOP w0.16: U17.84 77.37,38.23 77.77,38.63 77.77,40.08 79.51,41.81 R144.2
PTE7: length 81.8
  TOP w0.16: J2.14 27.58,54.71 27.58,52.15 29.57,50.16 32.93,50.16 35.07,48.02 54.18,48.02 55.99,46.2 71.14,46.2 72.24,47.3 74.77,47.3 75.08,46.99 v1(76.95,46.99) ; U17.59 v1(78.38,27.16)
  L3_MIX w0.16: v1(76.95,46.99) 76.95,45.94 78.1,44.79 78.1,28.2 78.38,27.92 v1(78.38,27.16)
PTE8: length 73.6
  TOP w0.16: v1(60,51.44) 36.77,51.44 35.24,52.97 35.24,54.68 J2.8 ; U17.26 67.37,21.41 63.46,17.5 v1(62.16,17.5) 62.16,16.48 R135.2
  L3_MIX w0.16: v1(60,51.44) 60,40.75 61.52,39.23 61.52,18.13 v1(62.16,17.5)
PTE9: length 45.5
  TOP w0.16: v1(68.39,22.07) 68.85,22.52 68.85,24 68.69,24.16 U17.23
  BOTTOM w0.16: v1(68.39,22.07) 64.81,18.48 61.02,18.48 60,17.47 53.87,17.47 45.4,9 39.93,9 36.94,6 36.94,3.99 J3.8
PTE10: length 55.4
  TOP w0.16: U17.6 v1(66.34,32.66)
  L3_MIX w0.16: v1(66.34,32.66) 66.34,21.82 v1(66.35,21.8)
  BOTTOM w0.16: J3.6 34.23,3.83 34.23,6.24 37.76,9.77 45.32,9.77 53.51,17.97 59.45,17.97 60.43,18.94 64.3,18.94 66.35,20.99 v1(66.35,21.8)
PTE11: length 51.5
  TOP w0.16: v1(80.34,6.32) 86.98,6.32 87.68,5.62 87.68,3.76 J5.14 ; U17.5 v1(80.28,33.16)
  L3_MIX w0.16: v1(80.34,6.32) 81.17,7.16 81.17,23.65 80.1,24.72 80.1,31.23 80.28,31.41 v1(80.28,33.16)
PTE12: length 45.3
  TOP w0.16: U17.19 66.55,26.16 v1(63.96,23.57) R159.2 ; J6.15 72.41,54.59 66.84,54.59 v1(65.75,53.5)
  L3_MIX w0.16: v1(65.75,53.5) 65.75,36.19 63.96,34.4 v1(63.96,23.57)
PTE13: length 41
  TOP w0.16: U17.7 v1(77.43,32.16)
  L3_MIX w0.16: J5.8 81.24,2.96 80.04,4.16 80.04,5.5 79.43,6.11 79.43,19.25 77.84,20.84 77.84,27.64 77.43,28.04 v1(77.43,32.16)
PTE14: length 34.8
  TOP w0.16: U17.17 v1(77.27,27.16)
  L3_MIX w0.16: J5.6 77.65,3.63 77.65,11.54 77.27,11.92 v1(77.27,27.16)
PTE15: length 40.3
  TOP w0.16: U17.2 v1(73.97,34.66)
  L3_MIX w0.16: J5.4 74.96,3.78 74.96,5.98 73.31,7.62 73.31,14.24 74.5,15.44 74.5,18.96 73.97,19.49 v1(73.97,34.66)
PTE16: length 37.5
  TOP w0.16: U17.1 71.24,35.16 v1(71.7,35.16)
  L3_MIX w0.16: J5.2 72.29,3.91 72.29,21.63 71.7,22.23 v1(71.7,35.16)
PWR_LED: length 1.4
  TOP w0.254: R56.1 D3.A
RGB_BLUE: length 61.7
  TOP w0.16: R156.2 v1(60.4,39.29) ; R95.2 v1(94.89,15.55)
  L3_MIX w0.16: v1(94.89,15.55) 94.89,17.42 94.61,17.7 v1(94.61,37.71)
  BOTTOM w0.16: v1(94.61,37.71) 92.48,39.84 86.46,39.84 85.56,38.94 77.14,38.94 75.86,37.66 69.17,37.66 68.19,38.65 63.81,38.65 63.16,39.29 v1(60.4,39.29)
RGB_GREEN: length 46.1
  TOP w0.16: R96.2 v1(93.81,11.72) ; R155.2 v1(60.3,21.89)
  L3_MIX w0.16: v1(93.81,11.72) 94.27,12.17 v1(94.27,17.12)
  BOTTOM w0.16: v1(60.3,21.89) 62.98,21.89 63.65,21.22 64.26,21.22 67.17,24.12 72.44,24.12 75.13,21.43 82.36,21.43 86.66,17.12 v1(94.27,17.12)
RGB_RED: length 50.9
  TOP w0.16: R154.2 v1(60.28,20.22) ; R97.2 v1(93.92,9.62)
  L3_MIX w0.16: v1(96.04,16.48) 96.04,11.74 v1(93.92,9.62)
  BOTTOM w0.16: v1(60.28,20.22) 61.85,20.22 62.55,19.51 64.02,19.51 64.76,20.25 64.76,20.92 67.43,23.59 71.27,23.59 74.53,20.33 82.55,20.33 86.4,16.48 v1(96.04,16.48)
RST_TGTMCU_B: length 169.6
  TOP w0.16: J104.3 6.77,47.82 5.84,48.75 5.84,49.84 5.09,50.59 R4.2 4.52,51.58 4.02,52.08 D1.C ; J104.3 U1.7 ; J104.3 8.92,48.99 10.85,48.99 R5.2 ; v1(68.47,44.67) 68.47,44.21 68.63,44.05 68.63,40.82 70.87,38.58 U17.97 ; v1(47.79,4.82) 46.74,3.77 34.33,3.77 J3.5 31.66,3.79 26.44,3.79 24.54,5.69 13.48,5.69 12.16,7.01 12.16,11.16 11.75,11.57 v1(11.75,12.79) ; R102.1 44.93,17.67 44.93,17.67 45.31,17.67 v1(46.6,16.38)
  L3_MIX w0.16: v1(47.79,4.82) 48.46,5.49 48.46,10.12 46.92,11.66 46.92,16.05 v1(46.6,16.38) 47.74,17.52 47.74,23.48 50.65,26.4 50.65,43.14 J14.10
  BOTTOM w0.16: v1(11.75,12.79) 11.75,16.3 10.09,17.96 10.09,22.76 6.26,26.59 6.26,46.33 J104.3 ; v1(68.47,44.67) 56.37,44.67 55.91,45.14 52.65,45.14 J14.10
SBC_CAN_RX: length 36.5
  TOP w0.16: U19.31 44.92,24.12 47.82,21.22 TP20.1 50.91,21.64 v1(58.37,21.64) ; R137.1 v1(60.31,35.94)
  L3_MIX w0.16: v1(58.37,21.64) 58.37,22.65 60.44,24.72 60.44,31.26 60.31,31.4 v1(60.31,35.94)
SBC_CAN_TX: length 40
  TOP w0.16: R136.1 v1(60.44,37.62) ; v1(59.13,20.97) 52,20.97 51.1,20.08 TP21.1 48.16,20.08 44.77,23.47 U19.30
  L3_MIX w0.16: v1(59.13,20.97) 59.13,22.64 60.99,24.49 60.99,37.07 v1(60.44,37.62)
SBC_CANH: length 12.7
  TOP w0.406: L4.1 v1(19.16,21.69) 19.98,20.87 U19.7
SBC_CANL: length 12.7
  TOP w0.406: U19.8 27.87,20.22 27.84,20.19 19.96,20.19 v1(19.16,19.39) L4.3
SBC_CS: length 63.8
  TOP w0.16: U19.25 39.5,20.22 v1(40.83,20.22) ; R129.1 90.18,30.25 v1(90.49,29.94)
  L3_MIX w0.16: v1(53.32,24.69) 53.32,24.16 51.58,22.42 51.58,16.7 50.39,15.5 v1(48.81,15.5)
  BOTTOM w0.16: v1(40.83,20.22) 42.91,18.14 45.57,18.14 48.2,15.5 v1(48.81,15.5) ; v1(90.49,29.94) 88.81,29.94 88.18,29.31 82.25,29.31 81.93,28.99 73.54,28.99 71.57,27.02 59.38,27.02 57.05,24.69 v1(53.32,24.69)
SBC_DBG: length 5.1
  TOP w0.16: U19.13 28.51,16.97 28.51,16.97 v1(28.05,16.97) 27.36,16.97 27.36,16.96 R105.2 R104.2
SBC_DBG_8V2: length 3.3
  TOP w0.16: R105.1 R113.2 25.99,13.97 25.51,13.48 D8.C
SBC_DBG_GND: length 1.3
  TOP w0.16: R104.1 R108.1
SBC_INT: length 23.1
  TOP w0.16: v1(47.15,22.71) 57.88,22.71 58.73,23.57 R159.1 ; R93.1 45.42,19.19 v1(46.99,17.61)
  L3_MIX w0.16: v1(46.99,17.61) 46.99,22.09 47.15,22.25 v1(47.15,22.71)
SBC_IO-0: length 26.8
  TOP w0.16: U19.12 23.06,17.62 v1(22.62,17.18) 20.17,14.73 20.17,13.15 19.48,12.45 15.21,12.45 12.76,14.9 v1(9.8,14.9) C46.1 R116.2
SBC_LIN-T1: length 9.5
  TOP w0.406: U19.4 28.88,22.82 28.51,23.19 27.08,23.19 25.55,24.72 v1(24.23,24.72) D6.A
SBC_LIN_RX: length 36
  TOP w0.16: v1(40.75,17.62) U19.21 ; R130.1 69.87,14.15 68.47,12.75 65.58,12.75 64.09,11.26 50.83,11.26 TP35.1 47.28,13.28 46.38,14.18 v1(46.38,15.42)
  BOTTOM w0.16: v1(40.75,17.62) 41.32,17.05 45.26,17.05 46.38,15.93 v1(46.38,15.42)
SBC_LIN_TX: length 32.6
  TOP w0.16: U19.20 40.47,16.97 v1(40.84,16.6) ; R131.1 68.2,14.18 67.34,13.33 65.32,13.33 63.78,11.79 53.07,11.79 TP37.1 49.63,14.36 49.26,14.74 v1(47.36,14.74)
  BOTTOM w0.16: v1(40.84,16.6) 41.89,15.55 45.37,15.55 46.18,14.74 v1(47.36,14.74)
SBC_MISO: length 67
  TOP w0.16: U19.28 45.27,22.17 48.51,18.93 TP23.1 51.62,18.93 52.06,19.37 v1(53.4,19.37) ; R125.2 v1(90.52,33.6)
  L3_MIX w0.16: v1(53.4,19.37) 53.4,23 54.07,23.67 54.07,29.89 v1(53.58,30.38)
  BOTTOM w0.16: v1(90.52,33.6) 88.38,33.6 87.86,33.09 85.84,33.09 84.91,32.16 80.21,32.16 79.32,33.04 77.02,33.04 76.17,32.2 66.53,32.2 66.53,32.19 66.14,32.19 66.14,32.2 55.4,32.2 v1(53.58,30.38)
SBC_MOSI: length 65.2
  TOP w0.16: v1(54.55,18.51) 52.62,18.51 51.89,17.79 TP25.1 45.08,21.52 U19.27 ; R126.2 v1(90.45,31.93)
  L3_MIX w0.16: v1(54.55,18.51) 54.55,22.2 57.3,24.95 v1(57.3,30.37)
  BOTTOM w0.16: v1(90.45,31.93) 88.36,31.93 87.87,32.42 86.34,32.42 85.55,31.64 84.66,31.64 84.62,31.67 84.2,31.67 84.17,31.64 77.45,31.64 77.12,31.3 58.23,31.3 v1(57.3,30.37)
SBC_MUX: length 65.8
  TOP w0.16: v1(19.22,13.26) R112.2 C44.1 ; v1(63.17,12.29) 64.84,13.97 R163.2
  L3_MIX w0.16: v1(19.22,13.26) 20.2,12.28 v1(20.2,6.19)
  BOTTOM w0.16: v1(63.17,12.29) 55.79,12.29 48.67,5.17 48.67,3.31 46.05,0.68 27.37,0.68 24.8,3.25 24.8,5.44 24.05,6.19 v1(20.2,6.19)
SBC_RST: length 4.1
  TOP w0.16: U19.23 TP24.1 41.4,18.33 42.06,17.67 R102.2
SBC_SAFE: length 9.6
  TOP w0.16: U19.5 v1(28.76,22.17) ; R73.2 24.46,27.7 24.45,27.7 R75.2 v1(24.45,25.78)
  BOTTOM w0.16: v1(24.45,25.78) 28.07,22.17 v1(28.76,22.17)
SBC_SCK: length 71.6
  TOP w0.16: R124.2 v1(90.55,35.28) ; v1(50.5,16.65) 48.88,16.65 44.66,20.87 U19.26
  L3_MIX w0.16: v1(50.5,16.65) 50.5,22.61 52.65,24.77 52.65,33.63 53.37,34.34 v1(53.37,34.81)
  BOTTOM w0.16: v1(53.37,34.81) 57.71,34.81 59.39,36.49 70.46,36.49 71.13,35.82 87.36,35.82 87.9,35.28 v1(90.55,35.28)
SBC_SPLIT: length 13
  TOP w0.406: R100.2 19.39,17.37 20.95,18.92 U19.10
SBC_VB: length 8
  TOP w0.254: U19.1 31,24.9 ; U19.1 31,24.77 ; U19.1 30.01,25.18 ; U19.1 31,25.04 ; Q1.3 33.81,27.46 ; Q1.3 33.26,26.37 ; Q1.3 32.83,26.37 ; Q1.3 32.72,27.46 ; Q1.3 33.7,26.37
SBC_VDD: length 32.2
  TOP w0.381: 31,30.47 C27.1 ; C27.1 31.95,31.23 ; C27.1 31.95,30.47 ; C27.1 31.31,31.99 ; C27.1 31.31,30.47 ; C27.1 31.95,31.99 ; 30.87,28.96 TP15.1 ; TP15.1 31.91,29.43 ; TP15.1 31.8,29.9 ; TP15.1 31.33,30 ; TP15.1 30.87,29.9 ; TP15.1 30.76,29.43 ; TP15.1 31.8,28.96 ; TP15.1 31.33,28.86
  TOP w0.432: 38.51,22.82 U19.29
  TOP w0.686: Q1.2 34.76,31.7 ; Q1.2 34.76,26.37 ; Q1.2 33.57,31.7 ; Q1.2 33.57,29.21 ; Q1.2 35.96,30.46 ; Q1.2 35.36,31.7 ; Q1.2 35.96,31.7 ; Q1.2 35.96,29.21 ; 33.25,33.75 J107.1 ; J107.1 35.15,33.75 ; J107.1 34.2,34.7 ; J107.1 34.2,32.8
  vias: v1(34.86,25.35)
SBC_VE: length 8
  TOP w0.254: U19.32 39.5,25.18 ; U19.32 38.51,24.63 ; U19.32 38.51,24.77 ; U19.32 38.51,25.04 ; Q1.1 36.7,26.37 ; Q1.1 35.72,27.46 ; Q1.1 36.81,27.46 ; Q1.1 35.83,26.37 ; Q1.1 36.27,26.37
SBC_VSENSE: length 5.8
  TOP w0.16: R110.2 42.75,15.35 42.75,15.36 C42.1 42.75,16.27 42.29,16.73 40.75,18.27 U19.22
SDA_EXTAL: length 5.4
  TOP w0.16: Y1.3 21.74,33.58 21.3,33.58 C23.1 20.55,34.32 20.55,36.2 U8.17
SDA_JTAG_TCLK: length 10.9
  TOP w0.16: J12.4 14.32,31.09 14.32,34.86 U8.12
SDA_JTAG_TDI: length 7.4
  TOP w0.16: U8.13 v1(17.23,37.07)
  BOTTOM w0.16: v1(17.23,37.07) 17.23,35.67 15.26,33.7 15.26,32.69 J12.8
SDA_JTAG_TDO: length 8.5
  TOP w0.16: U8.14 15.23,34.36 15.23,31.45 J12.6
SDA_JTAG_TMS: length 17
  TOP w0.16: J12.2 R77.2 18.91,26.27 20.15,27.51 20.15,30.35 18.31,32.18 18.31,36.73 U8.15
SDA_LED: length 2.7
  TOP w0.16: D2.C 22.74,42.45 21.91,42.45 U8.29
SDA_LED_R: length 1.3
  TOP w0.16: D2.A 24.28,43.99 R12.2
SDA_RST: length 18.4
  TOP w0.16: v1(26.69,34.76) 26.69,34.76 R62.1 25.69,35.76 25.69,35.76 R57.2 24.86,36.59 24.86,36.59 TP12.1 21.16,37.01 U8.19
  BOTTOM w0.16: v1(26.69,34.76) 17.63,34.76 J12.10
SDA_RST_LED: length 1.4
  TOP w0.16: D1.A R2.1
SDA_RST_TGTMCU_B: length 15.5
  TOP w0.16: U8.21 21.83,37.76 23.62,37.76 v1(24.18,38.33)
  BOTTOM w0.16: J105.2 20.63,46.19 20.63,44.7 21.73,43.6 21.73,39.66 23.06,38.33 v1(24.18,38.33)
SDA_RST_TGTMCU_J_B: length 11.6
  TOP w0.16: U1.2 R3.2 10.18,51.43 11.9,51.43 12.82,50.52 R5.1 J104.1 J105.1
SDA_RX_EN: length 2.7
  TOP w0.16: R16.1 32.02,44.44 R15.2 U4.5
SDA_SPI0_CS: length 9.7
  TOP w0.16: R38.2 TP7.1 25.78,40.15 25.42,39.79 23.98,39.79 22.69,38.5 22.5,38.5 U8.23
SDA_SPI0_RST_B: length 10.1
  TOP w0.16: U8.22 22.17,38.13 23.17,38.13 24.2,39.15 TP8.1 25.93,39.15 26.18,39.4 30.23,39.4 30.48,39.15 R41.2
SDA_SPI0_SCK: length 9.4
  TOP w0.16: v1(25.08,41.05) 22.63,41.05 22.1,40.52 ; v1(27.39,37.19) 28.04,37.19 28.48,37.62 U10.3
  BOTTOM w0.16: v1(25.08,41.05) 25.08,40.04 27.16,37.96 27.16,37.41 v1(27.39,37.19)
SDA_SPI0_SIN: length 11
  TOP w0.16: U2.5 27.52,47.85 27.19,47.52 27.19,45.54 23.59,41.95 22.12,41.95 U8.28
SDA_SPI0_SOUT: length 7.5
  TOP w0.16: U7.3 27.3,40.66 26.4,41.56 22.44,41.56 U8.27
SDA_SWD_EN: length 2.4
  TOP w0.16: R41.1 R47.1 U9.6
SDA_SWD_EN_B: length 18.4
  TOP w0.16: U8.16 v1(19.63,36.21) ; v1(35.58,37.16) R49.2
  BOTTOM w0.16: v1(19.63,36.21) 25.61,36.21 26.2,35.62 33.09,35.62 34.63,37.16 v1(35.58,37.16)
SDA_SWD_EN_B_R: length 2.7
  TOP w0.16: U9.1 R42.2 R49.1
SDA_SWD_EN_R: length 3.7
  TOP w0.16: U10.5 R52.2 31.03,38.13 R51.1 32.03,38.13 R47.2
SDA_SWD_OE: length 2.4
  TOP w0.16: R38.1 32.02,40.15 33.03,40.15 R35.1 U9.4
SDA_SWD_OE_B: length 19.5
  TOP w0.16: v1(25.27,37.82) 24.3,37.82 23.87,37.39 21.49,37.39 U8.20 ; R32.2 35.59,41.44 35.59,41 v1(35.85,40.73)
  BOTTOM w0.16: v1(35.85,40.73) 35.42,40.3 35.42,38.74 32.87,36.19 26.89,36.19 v1(25.27,37.82)
SDA_SWD_OE_B_R: length 2.8
  TOP w0.16: R32.1 R39.1 U9.3
SDA_SWD_OE_R: length 3.7
  TOP w0.16: R35.2 33.03,41.16 R31.1 R30.2 U7.5
SDA_USB_CONN_DN: length 13.2
  TOP w0.145: R25.1 15.73,43.97 15.33,44.37 13.41,44.37 12.54,43.49 8.57,43.49 U5.1 7.94,42.94 7.33,43.55 4.83,43.55 4.65,43.37 J7.2
SDA_USB_CONN_DP: length 13.5
  TOP w0.145: R21.1 15.94,44.18 15.45,44.66 13.29,44.66 12.42,43.79 8.68,43.79 U3.1 7.92,44.46 7.31,43.85 4.85,43.85 4.67,44.02 J7.3
SDA_USB_DN: length 2.1
  TOP w0.145: R25.2 17.08,42.65 17.65,42.08 17.65,41.94 U8.4
SDA_USB_DP: length 2.1
  TOP w0.145: R21.2 17.25,42.9 17.29,42.86 17.29,42.86 17.84,42.31 17.99,42.31 U8.3
SDA_USB_P5V_SENSE: length 3.8
  TOP w0.16: R14.2 22.79,44.04 22.79,44.04 R20.1 21.47,42.72 U8.30
SDA_USBSHIELD: length 9.3
  TOP w0.16: 6.21,40.76 L2.1 5.62,40.27
  TOP w1.016: J7.10 J7.8 J7.9
SDA_VOUT33: length 6.4
  TOP w0.254: C9.1 15.71,41.97 16.91,41.97 U8.5
  TOP w0.508: J9.2 15.18,41.44 C9.1
SDA_XTAL: length 5.3
  TOP w0.16: U8.18 20.95,36.51 22.61,36.51 C20.1 23.41,35.71 23.41,35.3 Y1.1
SPLIT: length 9.2
  TOP w0.406: R100.1 C40.1 12.75,17.37 12.33,16.94 12.31,16.94 11.72,16.35 R98.2 11.32,16.33 10.12,16.33 v1(9.5,16.95) 9.16,17.29 R92.2
SW1_RST_B: length 13.5
  TOP w0.16: SW5.4 SW5.2 11.15,53.63 v1(10.7,53.19) C1.1
  L3_MIX w0.16: J104.2 11.65,49.19 11.65,50.77 10.7,51.72 v1(10.7,53.19)
SWD_CLK_TGTMCU_BUF: length 21.8
  TOP w0.16: v1(30.07,37.47) 29.91,37.62 U10.4 ; J8.1 42.68,43.86 v1(42.68,40.06)
  BOTTOM w0.16: v1(30.07,37.47) 32.95,37.47 34.74,39.26 34.74,40.32 35.61,41.19 37.17,41.19 38.3,40.06 v1(42.68,40.06)
SWD_DIO_TGTMCU_BUF: length 23.9
  TOP w0.16: J106.1 41.33,42.73 39.23,44.83 35.6,44.83 33.08,47.35 v1(30.44,47.35) U2.2 ; U7.4 v1(30.02,40.66)
  BOTTOM w0.16: v1(30.44,47.35) 32.05,45.74 32.05,41.94 30.78,40.66 v1(30.02,40.66)
TC_EXTAL_TP: length 2.2
  TOP w0.16: U8.10 16.39,38.34 16.09,38.34 15.72,37.97 TP11.1
TC_SDA_USB_ID_TP: length 2.2
  TOP w0.16: TP6.1 5.88,44.67 J7.4
TC_XTAL_TP: length 3
  TOP w0.16: U8.9 16.19,38.85 15.83,38.85 TP10.1
TP_2102_A: length 1.6
  TOP w0.16: U1.3 v1(7.74,53.46)
TP_2102_B: length 1.2
  TOP w0.16: v1(6.24,50.29) 6.55,50.61 U1.6
UART1_RX_TGTMCU_BUF: length 7
  TOP w0.16: R24.1 35.45,43.57 30.66,43.57 30.29,43.94 U4.4
UART1_RX_TGTMCU_R: length 8.8
  TOP w0.16: v1(27.02,43.73) 27.83,43.73 28.04,43.94 U4.3 ; U8.25 22.89,40.6 23.67,40.6 23.88,40.39 25.35,40.39 v1(25.86,40.9)
  BOTTOM w0.16: v1(27.02,43.73) 27.02,42.06 v1(25.86,40.9)
UART1_TX_TGTMCU_BUF: length 6.4
  TOP w0.16: R18.1 32.26,46.83 U2.1
UART1_TX_TGTMCU_R: length 10.9
  TOP w0.16: U2.6 27.88,47.35 27.65,47.12 27.65,45.18 v1(27.12,44.65) ; U8.24 v1(23.29,40.08)
  BOTTOM w0.16: v1(27.12,44.65) 26.34,43.87 26.34,43.14 v1(23.29,40.08)
UART_RX: length 59.2
  TOP w0.16: R24.2 v1(34.07,43.05) ; R161.2 v1(84.66,44.35)
  BOTTOM w0.16: v1(34.07,43.05) 34.69,43.05 36.47,44.83 38.18,44.83 38.81,44.2 44.26,44.2 51.12,37.34 55.83,37.34 60.67,42.18 82.5,42.18 v1(84.66,44.35)
UART_TX: length 57.4
  TOP w0.16: R18.2 v1(36.98,44.16) ; R162.2 86.33,43.34 v1(86.33,44.28)
  BOTTOM w0.16: v1(36.98,44.16) 37.61,44.16 38.2,43.56 43.94,43.56 50.62,36.87 56.31,36.87 61.18,41.74 83.79,41.74 v1(86.33,44.28)
V_TGTMCU: length 14.7
  TOP w0.254: U7.6 29.81,41.66 v1(30.04,41.89) ; U4.6 v1(29.34,46.01) 29.05,46.31 U2.8 ; C8.1 v1(30.09,42.77) ; 2.98,50.98 R2.2 2.47,50.47 ; 0.98,50.98 C2.1 1.49,50.47 ; 3.5,51.1 R4.1 2.99,50.59 ; U10.6 29.8,38.62 29.88,38.7 v1(30.05,38.7) ; 2.99,49.63 C4.1 ; U1.8 8.14,50 v1(8.55,49.59)
  TOP w0.762: v1(38.48,42.57) v1(39.52,42.57) 39.52,39.41 38.86,38.76 SH1.1
  vias: v1(1.85,50.09) v1(2.77,50.09)
VCAN: length 7.1
  TOP w0.406: C31.1 27.76,22.18 28.42,21.52 U19.6
  TOP w0.635: C31.1 v1(24.23,22.18) C30.1
VREFH: length 16.2
  TOP w0.279: R99.2 63.08,31.47 64.89,29.66 U17.12
  TOP w0.508: R99.2 58.19,31.47 R103.2
  TOP w0.635: R103.2 C148.1 D7.C 55.9,34.07 55.67,34.29 R109.1
VSUP: length 61.7
  TOP w0.381: 27.79,13.2 R113.1 ; R113.1 28.74,13.2 ; R113.1 28.74,13.59 ; R113.1 28.74,14.35 ; R113.1 28.74,13.97 ; R113.1 28.11,13.2 ; D13.C 43.28,8.91 ; D13.C 41.58,9.69 ; D13.C 42.43,9.71 ; D13.C 41.58,8.12 ; D13.C 43.28,9.69 ; D13.C 41.58,8.91 ; D13.C 43.28,8.12 ; D13.C 42.43,8.11 ; TP36.1 32.48,11.82 ; TP36.1 32.38,11.35 ; TP36.1 31.91,11.25 ; TP36.1 31.91,12.39 ; TP36.1 32.38,12.29 ; TP36.1 31.44,11.35 ; TP36.1 31.44,12.29 ; TP36.1 31.34,11.82 ; D9.C 30.51,11.28 ; D9.C 29.65,12.08 ; D9.C 30.51,12.07 ; D9.C 28.8,12.07 ; D9.C 30.51,10.5 ; D9.C 29.65,10.48 ; D9.C 28.8,10.5 ; D9.C 28.8,11.28 ; 39.94,8.02 C128.1 ; C128.1 40.89,9.54 ; C128.1 40.89,8.78 ; C128.1 40.25,9.54 ; C128.1 40.25,8.02 ; C128.1 40.89,8.02 ; C47.1 33.77,12.67 ; C47.1 33.45,11.15 ; C47.1 33.77,11.15 ; C47.1 33.14,11.91 ; C47.1 33.14,11.15 ; C47.1 33.14,12.67
  TOP w0.406: R118.1 v1(11.32,10.4)
  TOP w0.457: v1(28.58,24.12) U19.2
  TOP w0.635: C29.1 v1(28.58,24.12)
  BOTTOM w0.381: v1(31.22,10.72) 29.79,9.29 25.5,9.29 22.37,12.42 13.34,12.42 v1(11.32,10.4)
  vias: v1(30.3,14.01) v1(31.06,14.03) v1(31.8,14.04)
VTRG_EN: length 4.6
  TOP w0.16: R69.2 R68.1 R70.2 U11.3
VTRG_FAULT_B: length 16.3
  TOP w0.16: U8.32 20.38,43.04 v1(20.38,43.64) ; v1(12.67,35.53) R60.2 11.22,35.53 U11.4
  BOTTOM w0.16: v1(20.38,43.64) 20.38,43.15 17.62,40.39 15.71,40.39 14.62,39.3 14.62,37.48 v1(12.67,35.53)
N20081740: length 1.7
  TOP w0.16: D4.C R73.1
N20083007: length 13.4
  TOP w0.16: U19.11 23.02,18.27 v1(21.42,16.67) 20.49,15.75 R112.1 R107.1
N20177646: length 109.7
  TOP w0.16: v1(25.02,1.84) 25.91,0.94 63.79,0.94 64.77,1.91 64.77,6.39 68.65,10.27 74.05,10.27 75.36,8.96 78.15,8.96 79.31,10.12 83.51,10.12 84.4,9.23 93.43,9.23 96.48,6.17 J5.19 ; v1(25.98,28) R75.1
  L3_MIX w0.16: v1(25.02,1.84) 25.02,12.46 25.98,13.42 v1(25.98,28)
N20181172: length 9.2
  TOP w0.16: R116.1 R118.2 SW6.2 SW6.4
N20279148: length 49.4
  TOP w0.16: R81.1 57.99,25.42 56.57,24.01 v1(49.55,24.01)
  L3_MIX w0.16: v1(49.55,24.01) 49.18,23.64 49.18,16.91 47.99,15.73 v1(47.99,14.04)
  BOTTOM w0.16: J3.2 29.18,3.86 29.18,6.43 30.12,7.37 33.35,7.37 37.64,11.65 45.61,11.65 v1(47.99,14.04)
N20279153: length 47.6
  TOP w0.16: R90.1 v1(59.87,30.38)
  L3_MIX w0.16: v1(59.87,30.38) 59.87,25.05 55.76,20.94 v1(55.76,19.37)
  BOTTOM w0.16: v1(55.76,19.37) 54.12,19.37 53.91,19.16 53.91,19.16 53.61,18.86 53.61,18.86 45.46,10.71 37.61,10.71 33.45,6.55 32.52,6.55 31.81,5.84 31.81,3.94 J3.4
N20335552: length 5
  TOP w0.16: R119.1 47.85,42.36 48.38,41.83 J14.6
N20335572: length 2.5
  TOP w0.16: J14.8 R120.1
N20337946: length 53.2
  TOP w0.16: R166.2 73.48,14.93 v1(74.22,14.19) ; R165.2 v1(82.99,44.37)
  L3_MIX w0.16: v1(82.99,44.37) 82.99,37.12 82.69,36.82 82.69,35.83 83.37,35.15 83.37,17.97 83.83,17.51 v1(83.83,14.27) ; J5.3 76.16,6.46 74.22,8.39 v1(74.22,14.19)
  BOTTOM w0.16: v1(83.83,14.27) 82.88,15.22 75.26,15.22 v1(74.22,14.19)
N20338949: length 54.4
  TOP w0.16: R168.2 71.69,14.25 71.69,14.25 v1(71.69,13.72) ; J5.1 v1(71.69,5.12) ; R167.2 v1(81.31,44.27)
  L3_MIX w0.16: v1(71.69,5.12) v1(71.69,13.72) ; v1(82.16,14.16) 82.16,17.98 82.56,18.37 82.56,34.56 81.92,35.2 81.92,42.97 81.31,43.58 v1(81.31,44.27)
  BOTTOM w0.16: v1(82.16,14.16) 81.83,14.48 76.37,14.48 75.61,13.72 v1(71.69,13.72)
N20340033: length 39.4
  L3_MIX w0.16: v1(100.79,33.66) 100.79,21.79 98.39,19.39 v1(98.39,16.32)
  BOTTOM w0.16: J5.9 86.35,7.69 91.21,7.69 98.39,14.86 v1(98.39,16.32) ; SH8.1 v1(100.79,33.66)
N20340042: length 27.6
  BOTTOM w0.16: J5.11 88.23,7.03 92.2,7.03 100.79,15.62 SH16.1
N20340793: length 27.5
  L3_MIX w0.16: v1(88.25,27.78) 88.25,39.35 88.86,39.96 J6.3
  BOTTOM w0.16: SH13.1 88.53,27.03 88.25,27.32 v1(88.25,27.78)
N20341595: length 96.9
  TOP w0.16: R133.1 88.69,16.31 v1(89.52,15.47) ; v1(66.52,13.96) R132.1
  L3_MIX w0.16: J1.13 48.22,50.78 50.04,48.96 50.04,26.77 46.51,23.24 46.51,17.38 45.86,16.73 45.86,9.25 v1(47.71,7.41)
  BOTTOM w0.16: v1(47.71,7.41) 54.26,13.96 v1(66.52,13.96) 70.79,13.96 71.69,14.86 73.57,14.86 74.46,15.75 83.15,15.75 83.43,15.47 v1(89.52,15.47)
